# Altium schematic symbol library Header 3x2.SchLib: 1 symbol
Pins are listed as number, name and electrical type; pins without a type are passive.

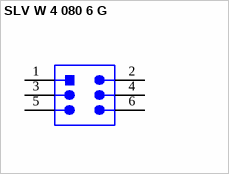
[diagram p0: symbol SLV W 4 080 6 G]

## SLV W 4 080 6 G
designator J?
Connector Header Through Hole 6 position 0.050" (1.27mm)
footprint SLV W 4 080 6 G (Sullins)
pins: 1, 2, 3, 4, 5, 6
1 alternate drawing of the same symbol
